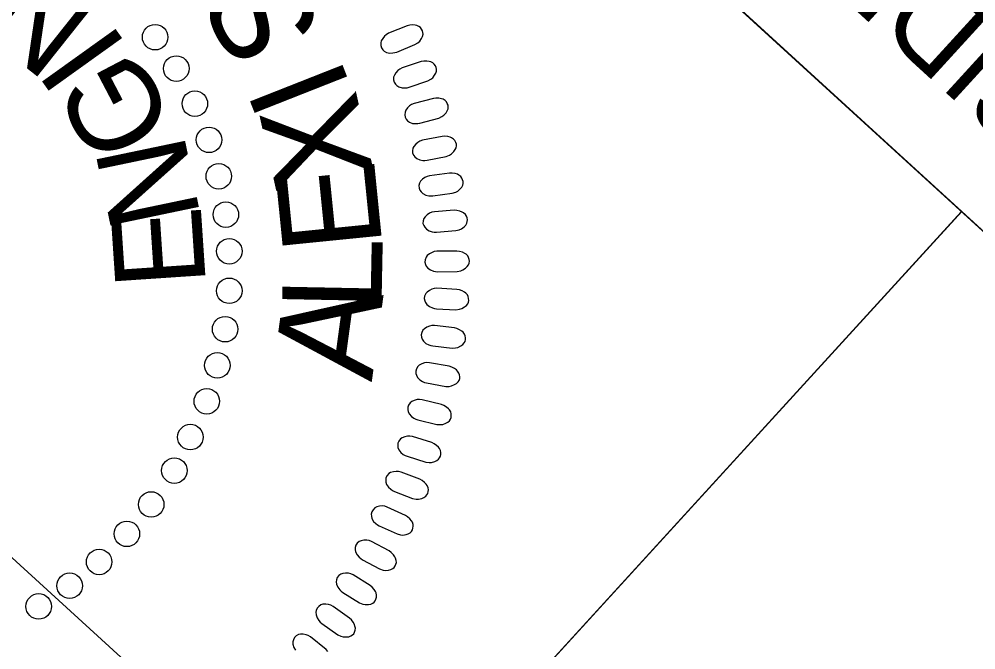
# Model space of a CAD drawing. Extents: x 475722 to 477703, y 499689 to 501633.
# Drawn here: x 475865.2 to 475925.2, y 500846 to 500885.6 of the extents above; entities that cross this region are included whole.
import ezdxf

# ---------------------------------------------------------------- set-up
doc = ezdxf.new("R2010")
doc.units = 0
for name, color, linetype in [('Sheet PE Seal Cell', 7, 'Continuous'), ('Sheet Plan CELL', 7, 'Continuous'), ('Sheet Sticker Exception Certification CELL', 7, 'Continuous'), ('Sheet Sticker Incomplete CELL', 7, 'Continuous')]:
    doc.layers.add(name, color=color, linetype=linetype)

msp = doc.modelspace()

# ---------------------------------------------------------------- linework, layer by layer
at = {"layer": 'Sheet PE Seal Cell'}
for points in [[(475888.867, 500883.526), (475890.001, 500883.993), (475890.189, 500884.111), (475890.299, 500884.212), (475890.413, 500884.38), (475890.478, 500884.512), (475890.508, 500884.646), (475890.506, 500884.758), (475890.481, 500884.869), (475890.42, 500884.965), (475890.347, 500885.064), (475890.252, 500885.138), (475890.12, 500885.197), (475890.023, 500885.223), (475889.859, 500885.228), (475889.671, 500885.215), (475889.514, 500885.175), (475888.35, 500884.704), (475888.201, 500884.618), (475888.09, 500884.523), (475887.976, 500884.38), (475887.889, 500884.223), (475887.853, 500884.103), (475887.857, 500883.935), (475887.896, 500883.789), (475887.989, 500883.666), (475888.075, 500883.588), (475888.215, 500883.508), (475888.417, 500883.463), (475888.61, 500883.469), (475888.74, 500883.491)], [(475889.641, 500881.32), (475890.802, 500881.714), (475890.997, 500881.82), (475891.113, 500881.914), (475891.238, 500882.075), (475891.311, 500882.203), (475891.35, 500882.335), (475891.354, 500882.446), (475891.336, 500882.559), (475891.282, 500882.658), (475891.215, 500882.762), (475891.125, 500882.843), (475890.996, 500882.909), (475890.902, 500882.94), (475890.738, 500882.956), (475890.549, 500882.955), (475890.391, 500882.925), (475889.199, 500882.527), (475889.046, 500882.452), (475888.928, 500882.364), (475888.805, 500882.228), (475888.709, 500882.077), (475888.665, 500881.959), (475888.659, 500881.791), (475888.688, 500881.643), (475888.774, 500881.515), (475888.855, 500881.432), (475888.99, 500881.343), (475889.189, 500881.285), (475889.381, 500881.279), (475889.513, 500881.292)], [(475890.31, 500879.061), (475891.494, 500879.383), (475891.696, 500879.476), (475891.817, 500879.562), (475891.952, 500879.715), (475892.032, 500879.837), (475892.079, 500879.966), (475892.092, 500880.078), (475892.081, 500880.192), (475892.033, 500880.294), (475891.973, 500880.403), (475891.887, 500880.487), (475891.764, 500880.562), (475891.671, 500880.599), (475891.509, 500880.625), (475891.32, 500880.636), (475891.16, 500880.616), (475889.945, 500880.294), (475889.788, 500880.228), (475889.665, 500880.148), (475889.534, 500880.02), (475889.428, 500879.876), (475889.377, 500879.76), (475889.36, 500879.594), (475889.38, 500879.444), (475889.458, 500879.31), (475889.533, 500879.222), (475889.662, 500879.125), (475889.857, 500879.055), (475890.049, 500879.037), (475890.181, 500879.041)], [(475890.761, 500876.735), (475891.963, 500876.981), (475892.17, 500877.062), (475892.297, 500877.141), (475892.441, 500877.285), (475892.528, 500877.403), (475892.584, 500877.528), (475892.602, 500877.638), (475892.599, 500877.753), (475892.557, 500877.858), (475892.503, 500877.969), (475892.424, 500878.06), (475892.305, 500878.142), (475892.216, 500878.185), (475892.055, 500878.221), (475891.867, 500878.243), (475891.707, 500878.234), (475890.474, 500877.989), (475890.313, 500877.933), (475890.185, 500877.861), (475890.046, 500877.742), (475889.931, 500877.604), (475889.873, 500877.493), (475889.846, 500877.326), (475889.856, 500877.176), (475889.926, 500877.037), (475889.996, 500876.945), (475890.118, 500876.84), (475890.308, 500876.758), (475890.498, 500876.727), (475890.631, 500876.724)], [(475891.131, 500874.5), (475892.346, 500874.67), (475892.558, 500874.738), (475892.689, 500874.808), (475892.841, 500874.943), (475892.936, 500875.055), (475893, 500875.176), (475893.026, 500875.286), (475893.03, 500875.4), (475892.994, 500875.507), (475892.948, 500875.622), (475892.874, 500875.717), (475892.76, 500875.807), (475892.674, 500875.856), (475892.516, 500875.901), (475892.33, 500875.936), (475892.169, 500875.936), (475890.923, 500875.769), (475890.758, 500875.723), (475890.626, 500875.659), (475890.481, 500875.549), (475890.358, 500875.419), (475890.292, 500875.311), (475890.255, 500875.147), (475890.256, 500874.996), (475890.316, 500874.854), (475890.381, 500874.757), (475890.497, 500874.645), (475890.681, 500874.55), (475890.869, 500874.508), (475891.001, 500874.497)], [(475891.346, 500872.23), (475892.569, 500872.324), (475892.785, 500872.377), (475892.92, 500872.44), (475893.081, 500872.565), (475893.184, 500872.671), (475893.254, 500872.788), (475893.286, 500872.895), (475893.297, 500873.009), (475893.269, 500873.119), (475893.229, 500873.236), (475893.163, 500873.336), (475893.055, 500873.432), (475892.971, 500873.486), (475892.816, 500873.542), (475892.633, 500873.588), (475892.472, 500873.599), (475891.218, 500873.51), (475891.051, 500873.475), (475890.915, 500873.419), (475890.763, 500873.318), (475890.633, 500873.196), (475890.561, 500873.093), (475890.512, 500872.932), (475890.504, 500872.78), (475890.555, 500872.635), (475890.613, 500872.534), (475890.722, 500872.415), (475890.9, 500872.309), (475891.085, 500872.255), (475891.216, 500872.235)], [(475891.428, 500869.747), (475892.655, 500869.763), (475892.873, 500869.803), (475893.012, 500869.857), (475893.18, 500869.972), (475893.288, 500870.071), (475893.367, 500870.184), (475893.406, 500870.289), (475893.424, 500870.401), (475893.402, 500870.513), (475893.371, 500870.633), (475893.31, 500870.736), (475893.208, 500870.839), (475893.128, 500870.898), (475892.977, 500870.964), (475892.797, 500871.021), (475892.638, 500871.042), (475891.381, 500871.032), (475891.211, 500871.008), (475891.073, 500870.96), (475890.914, 500870.869), (475890.776, 500870.755), (475890.698, 500870.657), (475890.639, 500870.499), (475890.622, 500870.349), (475890.664, 500870.2), (475890.715, 500870.096), (475890.816, 500869.97), (475890.987, 500869.853), (475891.168, 500869.788), (475891.298, 500869.76)], [(475891.348, 500867.421), (475892.574, 500867.361), (475892.794, 500867.387), (475892.936, 500867.432), (475893.111, 500867.536), (475893.226, 500867.627), (475893.311, 500867.735), (475893.356, 500867.838), (475893.381, 500867.949), (475893.367, 500868.062), (475893.343, 500868.183), (475893.289, 500868.29), (475893.194, 500868.399), (475893.117, 500868.463), (475892.971, 500868.538), (475892.795, 500868.606), (475892.637, 500868.637), (475891.382, 500868.707), (475891.211, 500868.693), (475891.07, 500868.654), (475890.906, 500868.573), (475890.761, 500868.468), (475890.676, 500868.375), (475890.609, 500868.221), (475890.582, 500868.073), (475890.614, 500867.922), (475890.659, 500867.815), (475890.752, 500867.682), (475890.915, 500867.555), (475891.092, 500867.478), (475891.219, 500867.442)], [(475891.115, 500865.086), (475892.335, 500864.948), (475892.556, 500864.961), (475892.701, 500864.996), (475892.882, 500865.089), (475893.002, 500865.174), (475893.094, 500865.276), (475893.145, 500865.375), (475893.178, 500865.485), (475893.17, 500865.598), (475893.154, 500865.721), (475893.106, 500865.832), (475893.019, 500865.946), (475892.946, 500866.015), (475892.805, 500866.099), (475892.634, 500866.178), (475892.478, 500866.219), (475891.23, 500866.366), (475891.059, 500866.363), (475890.915, 500866.334), (475890.746, 500866.263), (475890.595, 500866.168), (475890.505, 500866.08), (475890.428, 500865.931), (475890.391, 500865.784), (475890.414, 500865.631), (475890.452, 500865.521), (475890.536, 500865.384), (475890.692, 500865.246), (475890.863, 500865.159), (475890.988, 500865.115)], [(475890.725, 500862.767), (475891.934, 500862.553), (475892.156, 500862.551), (475892.302, 500862.578), (475892.489, 500862.659), (475892.614, 500862.736), (475892.712, 500862.832), (475892.769, 500862.928), (475892.809, 500863.035), (475892.808, 500863.149), (475892.8, 500863.272), (475892.759, 500863.386), (475892.679, 500863.506), (475892.611, 500863.579), (475892.475, 500863.671), (475892.309, 500863.761), (475892.156, 500863.811), (475890.92, 500864.038), (475890.749, 500864.045), (475890.603, 500864.025), (475890.431, 500863.965), (475890.274, 500863.879), (475890.178, 500863.797), (475890.092, 500863.653), (475890.047, 500863.509), (475890.06, 500863.355), (475890.091, 500863.244), (475890.167, 500863.1), (475890.313, 500862.953), (475890.478, 500862.855), (475890.6, 500862.804)], [(475890.179, 500860.455), (475891.372, 500860.166), (475891.593, 500860.15), (475891.742, 500860.168), (475891.933, 500860.237), (475892.063, 500860.306), (475892.166, 500860.396), (475892.23, 500860.488), (475892.275, 500860.593), (475892.282, 500860.706), (475892.281, 500860.83), (475892.248, 500860.945), (475892.175, 500861.07), (475892.112, 500861.147), (475891.983, 500861.248), (475891.822, 500861.348), (475891.673, 500861.408), (475890.453, 500861.712), (475890.283, 500861.73), (475890.137, 500861.718), (475889.961, 500861.669), (475889.799, 500861.593), (475889.698, 500861.518), (475889.603, 500861.379), (475889.549, 500861.238), (475889.552, 500861.084), (475889.576, 500860.97), (475889.643, 500860.823), (475889.78, 500860.667), (475889.938, 500860.559), (475890.057, 500860.5)], [(475889.503, 500858.162), (475890.675, 500857.799), (475890.895, 500857.77), (475891.044, 500857.778), (475891.239, 500857.835), (475891.373, 500857.895), (475891.483, 500857.979), (475891.551, 500858.067), (475891.604, 500858.168), (475891.618, 500858.281), (475891.624, 500858.404), (475891.599, 500858.522), (475891.534, 500858.651), (475891.476, 500858.732), (475891.353, 500858.841), (475891.199, 500858.951), (475891.054, 500859.019), (475889.856, 500859.399), (475889.687, 500859.428), (475889.54, 500859.427), (475889.362, 500859.388), (475889.195, 500859.323), (475889.089, 500859.253), (475888.986, 500859.121), (475888.922, 500858.984), (475888.917, 500858.83), (475888.933, 500858.714), (475888.99, 500858.564), (475889.117, 500858.4), (475889.269, 500858.282), (475889.384, 500858.215)], [(475888.71, 500855.962), (475889.857, 500855.525), (475890.076, 500855.482), (475890.225, 500855.48), (475890.423, 500855.525), (475890.56, 500855.577), (475890.674, 500855.654), (475890.749, 500855.737), (475890.808, 500855.835), (475890.828, 500855.946), (475890.843, 500856.069), (475890.825, 500856.188), (475890.768, 500856.321), (475890.715, 500856.405), (475890.599, 500856.522), (475890.453, 500856.641), (475890.312, 500856.719), (475889.14, 500857.174), (475888.973, 500857.213), (475888.827, 500857.22), (475888.646, 500857.193), (475888.476, 500857.138), (475888.366, 500857.076), (475888.255, 500856.95), (475888.183, 500856.817), (475888.167, 500856.664), (475888.177, 500856.548), (475888.224, 500856.394), (475888.341, 500856.222), (475888.484, 500856.095), (475888.595, 500856.022)], [(475887.761, 500853.798), (475888.878, 500853.291), (475889.093, 500853.234), (475889.242, 500853.223), (475889.443, 500853.255), (475889.583, 500853.299), (475889.702, 500853.368), (475889.782, 500853.446), (475889.846, 500853.54), (475889.874, 500853.65), (475889.896, 500853.772), (475889.886, 500853.892), (475889.838, 500854.028), (475889.791, 500854.116), (475889.682, 500854.239), (475889.543, 500854.367), (475889.407, 500854.454), (475888.266, 500854.981), (475888.102, 500855.03), (475887.957, 500855.047), (475887.775, 500855.031), (475887.601, 500854.987), (475887.488, 500854.932), (475887.369, 500854.814), (475887.289, 500854.686), (475887.263, 500854.533), (475887.265, 500854.417), (475887.303, 500854.261), (475887.408, 500854.082), (475887.544, 500853.946), (475887.65, 500853.865)], [(475886.704, 500851.671), (475887.786, 500851.094), (475887.997, 500851.024), (475888.145, 500851.004), (475888.348, 500851.024), (475888.49, 500851.058), (475888.613, 500851.12), (475888.698, 500851.193), (475888.768, 500851.283), (475888.803, 500851.391), (475888.833, 500851.51), (475888.83, 500851.631), (475888.79, 500851.771), (475888.748, 500851.861), (475888.648, 500851.99), (475888.517, 500852.128), (475888.387, 500852.222), (475887.282, 500852.82), (475887.121, 500852.88), (475886.977, 500852.905), (475886.794, 500852.901), (475886.618, 500852.868), (475886.503, 500852.82), (475886.375, 500852.709), (475886.287, 500852.587), (475886.253, 500852.436), (475886.247, 500852.32), (475886.275, 500852.161), (475886.369, 500851.977), (475886.496, 500851.832), (475886.596, 500851.745)], [(475885.478, 500849.619), (475886.523, 500848.976), (475886.729, 500848.892), (475886.875, 500848.863), (475887.079, 500848.87), (475887.223, 500848.895), (475887.35, 500848.949), (475887.438, 500849.017), (475887.514, 500849.102), (475887.556, 500849.208), (475887.593, 500849.325), (475887.598, 500849.446), (475887.567, 500849.587), (475887.531, 500849.68), (475887.439, 500849.816), (475887.317, 500849.961), (475887.193, 500850.064), (475886.127, 500850.729), (475885.971, 500850.799), (475885.829, 500850.834), (475885.646, 500850.841), (475885.468, 500850.819), (475885.349, 500850.778), (475885.216, 500850.676), (475885.12, 500850.559), (475885.076, 500850.411), (475885.063, 500850.296), (475885.082, 500850.136), (475885.164, 500849.945), (475885.281, 500849.793), (475885.376, 500849.7)], [(475884.156, 500847.678), (475885.158, 500846.97), (475885.358, 500846.874), (475885.503, 500846.835), (475885.706, 500846.83), (475885.852, 500846.846), (475885.982, 500846.891), (475886.074, 500846.954), (475886.156, 500847.034), (475886.204, 500847.137), (475886.248, 500847.252), (475886.26, 500847.372), (475886.238, 500847.515), (475886.208, 500847.61), (475886.125, 500847.751), (475886.013, 500847.904), (475885.895, 500848.014), (475884.873, 500848.745), (475884.722, 500848.825), (475884.582, 500848.868), (475884.4, 500848.887), (475884.222, 500848.877), (475884.1, 500848.843), (475883.96, 500848.749), (475883.858, 500848.638), (475883.804, 500848.493), (475883.785, 500848.379), (475883.792, 500848.218), (475883.862, 500848.023), (475883.97, 500847.864), (475884.059, 500847.765)]]:
    msp.add_lwpolyline(points, close=True, dxfattribs=at)
msp.add_lwpolyline([(475884.538, 500845.917), (475884.429, 500846.035), (475883.454, 500846.829), (475883.308, 500846.918), (475883.171, 500846.97), (475882.99, 500847), (475882.812, 500847), (475882.689, 500846.975), (475882.543, 500846.891), (475882.434, 500846.786), (475882.371, 500846.645), (475882.344, 500846.532), (475882.343, 500846.37), (475882.399, 500846.171), (475882.497, 500846.006)], dxfattribs=at)
for centre in [(475873.693, 500884.461), (475875.02, 500882.491), (475876.189, 500880.289), (475877.08, 500878.017), (475877.689, 500875.733), (475878.134, 500873.329), (475878.349, 500871.027), (475878.346, 500868.546), (475878.087, 500866.139), (475877.598, 500863.871), (475876.937, 500861.614), (475875.909, 500859.369), (475874.903, 500857.266), (475873.447, 500855.143), (475871.923, 500853.298), (475870.182, 500851.536), (475868.331, 500850.044), (475866.388, 500848.744)]:
    msp.add_circle(centre, 0.801, dxfattribs=at)
at = {"layer": 'Sheet Plan CELL'}
msp.add_line((475848.428, 500790.468), (475924.281, 500873.498), dxfattribs=at)
for points in [[(475848.428, 500790.468), (475774.607, 500857.906), (475850.494, 500940.973), (475924.324, 500873.526)], [(475922.287, 500722.978), (475848.428, 500790.468), (475924.324, 500873.526), (475998.157, 500806.027)]]:
    msp.add_lwpolyline(points, close=True, dxfattribs=at)
at = {"layer": 'Sheet Sticker Exception Certification CELL'}
msp.add_line((475998.157, 500806.027), (475850.485, 500940.964), dxfattribs=at)
msp.add_line((475998.157, 500806.027), (475850.485, 500940.964), dxfattribs=at)
at = {"layer": 'Sheet Sticker Incomplete CELL'}
msp.add_lwpolyline([(475940.631, 500782.412), (475924.779, 500765.064), (475816.261, 500864.224), (475832.113, 500881.573)], close=True, dxfattribs=at)

# ---------------------------------------------------------------- texts
at = {"layer": 'Sheet PE Seal Cell'}
for s, height, rotation, p in [('N', 5.669, 141.48434, (475870.314, 500886.043)), ('S', 6.236, 118.36738, (475884.466, 500884.996)), ('I', 5.669, 125.60474, (475872.028, 500883.836)), ('G', 5.669, 117.66494, (475875.043, 500878.793)), ('I', 6.236, 111.52172, (475886.022, 500881.28)), ('X', 6.236, 102.5744, (475887.464, 500875.817)), ('N', 5.669, 101.78535, (475876.566, 500873.204)), ('E', 6.236, 95.72874, (475887.969, 500871.328)), ('E', 5.669, 93.84555, (475876.887, 500868.907)), ('L', 6.236, 88.88309, (475887.894, 500867.223)), ('A', 6.236, 82.26341, (475887.286, 500862.793))]:
    msp.add_text(s, height=height, rotation=rotation, dxfattribs=at).set_placement(p)
at = {"layer": 'Sheet Sticker Exception Certification CELL'}
for s, p in [('UNLESS ALL SIGNATURES COMPLETED', (475999.261, 500830.953)), ('UNLESS ALL SIGNATURES COMPLETED', (475999.261, 500830.953)), ('DOCUMENT NOT CONSIDERED FINAL', (475989.581, 500827.877)), ('DOCUMENT NOT CONSIDERED FINAL', (475989.581, 500827.877))]:
    msp.add_text(s, height=5.5, rotation=137.57996, dxfattribs=at).set_placement(p)
at = {"layer": 'Sheet Sticker Incomplete CELL'}
for s, height, p in [('INCOMPLETE PLANS', 11.52, (475926.132, 500779.812)), ('DO NOT USE FOR R/W ACQUISITION', 5.76, (475928.421, 500787.135))]:
    msp.add_text(s, height=height, rotation=137.57996, dxfattribs=at).set_placement(p)

doc.saveas('drawing.dxf')
